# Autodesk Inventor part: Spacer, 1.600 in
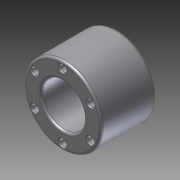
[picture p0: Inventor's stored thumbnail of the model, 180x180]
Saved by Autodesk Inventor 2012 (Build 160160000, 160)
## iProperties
Created: 2010-12
Part Number: Spacer, 1.600 in
Document SubType Name: Modeling
Designer: Alex
Density: 1 g/cm^3
Material: Default
Author: Alex
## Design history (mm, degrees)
sketch "Sketch1"
  geometry: C1 r 28.575 at (0, 0); C2 r 15.875 at (0, 0); 7 further points
  constraints: 2 centre point, 7 other
  dimensions: "d0" = 57.15 diameter of C1; "d1" = 31.75 diameter of C2; "d2" = 23.8125 distance of point (0, 0) point (0, 23.812); "d5" = 360 deg dimension on point (0, 0) point (0, 23.812) (derived)
extrude "Extrusion1" new body sketch "Sketch1" distance "d7" = 40.64; taper "d8" = 0 deg
hole "Hole1" sketch "Sketch1" diameter "d9" = 5.1816; stored, may be unused: countersink angle "d13" = 82 deg, drill point angle "d15" = 118 deg; dims "d10" = 19.05, "d11" = 9.525, "d12" = 6.35, "d14" = 25.4
fillet "Fillet1" dims "d16" = 1.5875
fillet "Fillet2" dims "d17" = 0.79375
fillet "Fillet3" dims "d18" = 0.79375
body "Solid1"
